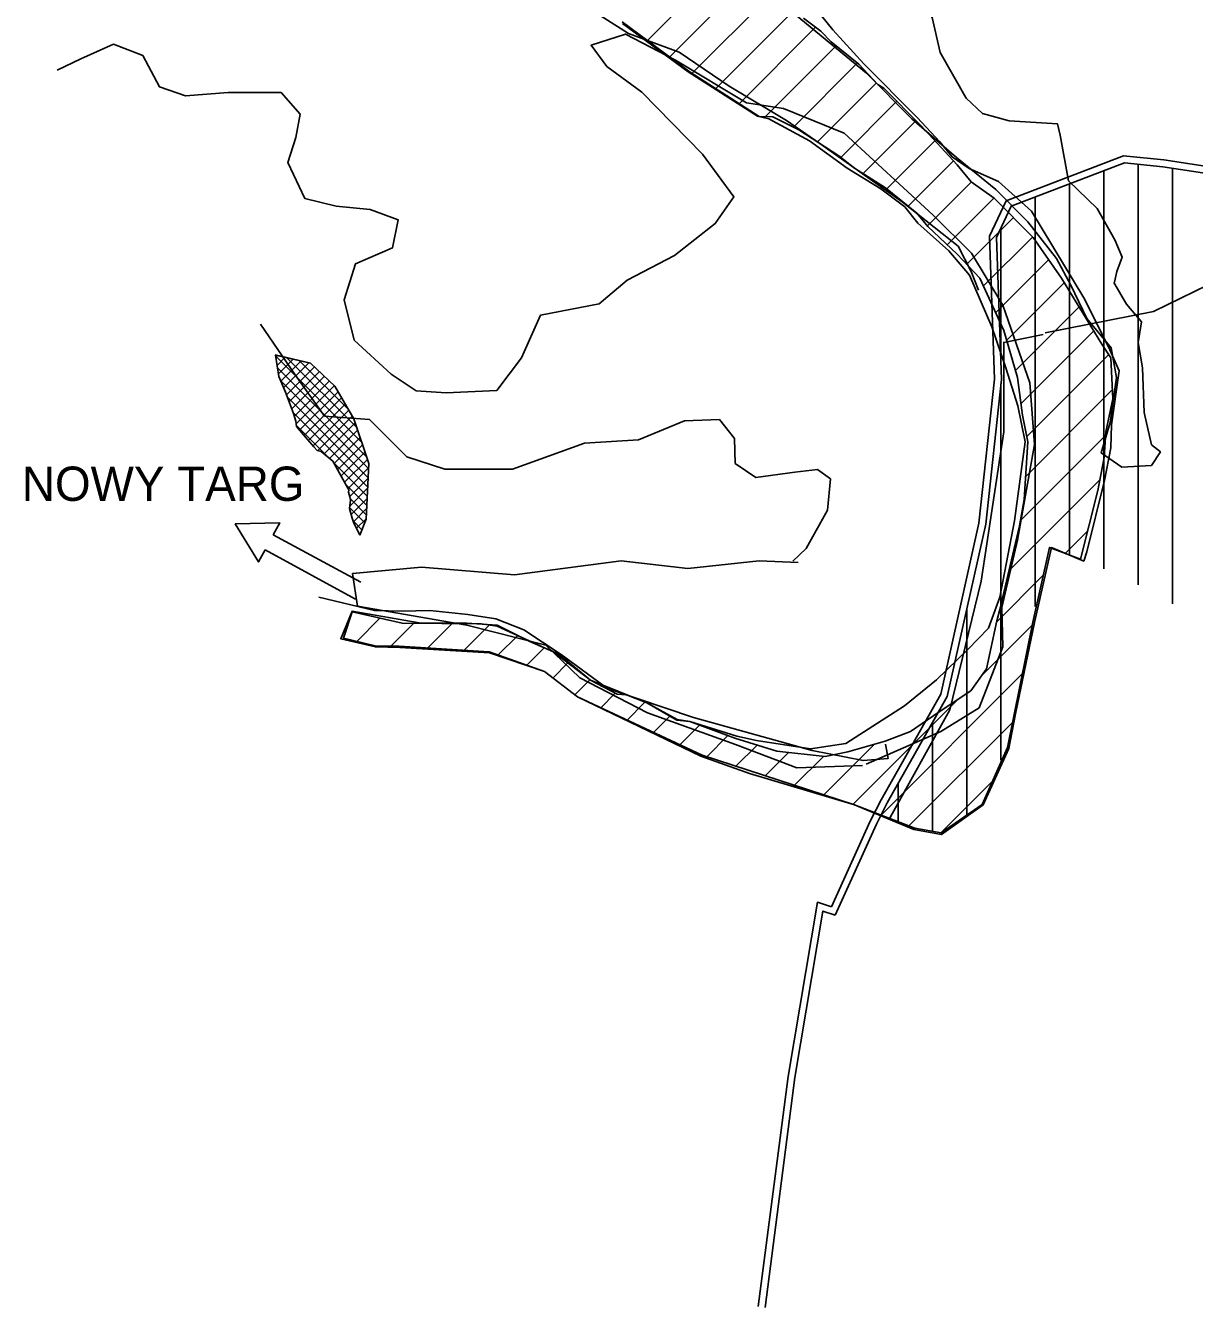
# Model space of a CAD drawing. Extents: x -562861 to -547287, y 190696 to 208158.
# Drawn here: x -559895 to -558190, y 195518 to 197388 of the extents above; entities that cross this region are included whole.
import ezdxf

# ---------------------------------------------------------------- set-up
doc = ezdxf.new("R2010")
doc.units = 0
for name, color, linetype in [('EKO - gr-OChK', 7, 'Continuous'), ('EKO - gr-PPK', 7, 'Continuous'), ('EKO - gr-PPK-otulina', 7, 'Continuous'), ('EKO - strefa ekologiczna', 7, 'Continuous'), ('EKO1 - ter_erozyjne', 7, 'Continuous'), ('EKO2 - erozja full', 7, 'Continuous'), ('natura_2000', 7, 'Continuous'), ('RZGW_100letnia', 7, 'Continuous'), ('str zal bezposr_zagr', 7, 'Continuous'), ('strzałki', 7, 'Continuous')]:
    doc.layers.add(name, color=color, linetype=linetype)

msp = doc.modelspace()

# ---------------------------------------------------------------- linework, layer by layer
at = {"layer": 'EKO - gr-OChK'}
for points in [[(-558719.6, 196102.3), (-558663.1, 196227.2), (-558647.2, 196258.5), (-558560.2, 196412.6), (-558504.6, 196662), (-558481.8, 196871.9), (-558489, 197080.5), (-558464.7, 197132.3), (-558293.5, 197197.8), (-558234.9, 197191.8), (-558082.6, 197168.6)], [(-558826.5, 195519.2), (-558783.2, 195854.8), (-558740.2, 196109), (-558719.6, 196102.3)]]:
    msp.add_lwpolyline(points, dxfattribs=at)
at = {"layer": 'EKO - gr-PPK'}
for p, q in [((-558272.5, 196571.8), (-558272.5, 197185.6)), ((-558222.5, 196544.2), (-558222.5, 197179.8)), ((-558322.5, 196595.1), (-558322.5, 197176)), ((-558372.5, 196615.6), (-558372.5, 197156.9)), ((-558422.5, 196540.1), (-558422.5, 197137.8)), ((-558472.5, 196892.2), (-558472.5, 197092.2)), ((-558472.5, 196316.2), (-558472.5, 196865)), ((-558522.5, 196235.8), (-558522.5, 196535.9)), ((-558572.5, 196213.4), (-558572.5, 196370.5)), ((-558622.5, 196225.8), (-558622.5, 196282))]:
    msp.add_line(p, q, dxfattribs=at)
for points in [[(-558085.3, 197158.9), (-558236.2, 197181.9), (-558292.2, 197187.6), (-558457.4, 197124.4), (-558479, 197078.4), (-558471.8, 196871.5), (-558494.8, 196660.4), (-558550.8, 196408.9), (-558638.4, 196253.8), (-558654.1, 196222.8)], [(-558654.1, 196222.8), (-558714.2, 196090.1)], [(-558714.2, 196090.1), (-558732.3, 196095.9), (-558773.3, 195853.3), (-558816.5, 195517.9)]]:
    msp.add_lwpolyline(points, dxfattribs=at)
at = {"layer": 'EKO - gr-PPK-otulina'}
for points in [[(-559082.7, 197418.3), (-559015.9, 197376.2), (-558941.9, 197348.8), (-558868.8, 197299.3), (-558785.2, 197249.1), (-558736.9, 197215.7), (-558616.8, 197130.4), (-558535.1, 197066.1), (-558516.1, 197028.8), (-558505.1, 197001.7)], [(-558641.1, 196339.4), (-558637.1, 196318.6), (-558673.7, 196315.6), (-558748, 196330.4), (-558921.3, 196378.6), (-559046.4, 196420.7), (-559114, 196470.4), (-559168.5, 196506.2), (-559209.4, 196522.3), (-559250.2, 196528.5), (-559305.9, 196534.7), (-559346.8, 196533.4), (-559386.4, 196534.7), (-559467.7, 196553.9)]]:
    msp.add_lwpolyline(points, dxfattribs=at)
at = {"layer": 'EKO - strefa ekologiczna'}
for points in [[(-558557.5, 197591.2), (-558592.4, 197585.8), (-558636.9, 197559.6), (-558639.5, 197525.6), (-558618.6, 197473.3), (-558572.8, 197399.3), (-558561, 197348.3), (-558523.1, 197281.6), (-558499.6, 197259.4), (-558460.4, 197248.9), (-558389.8, 197244.3), (-558385.9, 197228), (-558374.1, 197161.3), (-558332.3, 197120.7), (-558306.2, 197075), (-558295.7, 197050.1), (-558303.5, 197029.2), (-558307.1, 197013.3)], [(-558307.8, 197012.9), (-558289.5, 196981.5), (-558267.3, 196955.4), (-558272.5, 196925.3), (-558266, 196888.7), (-558263.4, 196823.3), (-558252.9, 196776.2), (-558239.9, 196765.7), (-558252.9, 196746.1), (-558296.1, 196743.5), (-558326.1, 196764.4), (-558313.1, 196808.9), (-558303.9, 196874.3), (-558311.8, 196917.4), (-558347.1, 196960.6), (-558370.6, 197009), (-558391.5, 197048), (-558433.3, 197101.6), (-558480.1, 197148.4), (-558537.6, 197195.5), (-558602.7, 197251.5), (-558668.7, 197318.3), (-558802.8, 197429)], [(-559282.1, 196852), (-559208.2, 196855.3), (-559172.1, 196902.9), (-559144.2, 196965.3), (-559058.9, 196981.7), (-559017.9, 197016.2), (-558948.9, 197052.3), (-558889.3, 197098.9), (-558862, 197137.7), (-558907.9, 197200.1), (-558996.5, 197290.4), (-559047.4, 197328.2), (-559070.4, 197358.9), (-559020.3, 197375.2), (-558947.3, 197337.5), (-558843.9, 197275.2), (-558789.8, 197266.9), (-558701.1, 197230.8), (-558571.5, 197111), (-558515.7, 197055.5), (-558469.7, 196979.9), (-558430.3, 196866.6), (-558423.8, 196776.8), (-558448.4, 196637.2), (-558471.4, 196538.7), (-558469.7, 196481.3), (-558504.2, 196392.6), (-558560, 196358), (-558669, 196310.1)], [(-559849.3, 197322.8), (-559814.8, 197339.2), (-559767.2, 197360.5), (-559724.6, 197344.1), (-559699.9, 197298.2), (-559662.2, 197285), (-559599.8, 197289.9), (-559522.7, 197289.9), (-559494.8, 197258.7), (-559501.4, 197224.3), (-559512.8, 197188.1), (-559488.2, 197135.6), (-559442.3, 197124.1), (-559393, 197119.2), (-559352, 197104.4), (-559360.2, 197063.3), (-559414.4, 197040.4), (-559430.8, 196987.8), (-559416, 196928.7), (-559361.9, 196879.4), (-559325.8, 196854.8), (-559282.1, 196852)], [(-558776, 196606.2), (-558756.8, 196625), (-558725.8, 196681), (-558721.3, 196726.4), (-558740.2, 196740), (-558773.4, 196736.2), (-558830.1, 196728.6), (-558860.3, 196749), (-558861.1, 196785.3), (-558883.3, 196812.9), (-558934.2, 196811.3), (-559001.5, 196783.4), (-559080.2, 196778.4), (-559185.3, 196740.7), (-559283.7, 196740.7), (-559339.5, 196758.7), (-559393.7, 196812.9), (-559459.3, 196817.9), (-559502, 196878.3), (-559552.9, 196952.2)], [(-558674.3, 196308.5), (-558770.1, 196305.1), (-558859.9, 196339.2), (-558988.1, 196385), (-559087, 196436.3), (-559136.4, 196484), (-559251.8, 196513.3), (-559411.1, 196540.8), (-559418.5, 196588.4), (-559317.7, 196597.6), (-559182.2, 196586.6), (-559026.5, 196606.7), (-558929.5, 196595.8), (-558825.1, 196606.7), (-558768.3, 196604.5)]]:
    msp.add_lwpolyline(points, dxfattribs=at)
at = {"layer": 'EKO1 - ter_erozyjne'}
for points in [[(-559531.2, 196907.2), (-559479.9, 196895.1), (-559444.3, 196861.5), (-559416.6, 196814), (-559394.9, 196748.8), (-559398.8, 196667.7), (-559407.7, 196644.5)], [(-559407.7, 196644.5), (-559398.8, 196667.7), (-559394.9, 196748.8), (-559416.6, 196814), (-559444.3, 196861.5), (-559479.9, 196895.1), (-559530.9, 196907.1)], [(-559530.9, 196907.1), (-559525.9, 196875.8), (-559516.4, 196852.9), (-559504.7, 196822), (-559501.2, 196810.9), (-559500.3, 196803), (-559490.1, 196790.9), (-559474.8, 196773.3), (-559470.1, 196767.9)], [(-559470.1, 196767.9), (-559464.2, 196766.5), (-559447.1, 196752.4), (-559425.3, 196713), (-559424, 196710.7), (-559424.6, 196707.1), (-559422.4, 196700.4), (-559421.5, 196695.4), (-559423.1, 196683.2), (-559419.2, 196669.4), (-559417.1, 196663.5), (-559407.7, 196644.5)]]:
    msp.add_lwpolyline(points, dxfattribs=at)
at = {"layer": 'EKO2 - erozja full'}
for p, q in [((-559530.6, 196905.4), (-559405.3, 196780)), ((-559530.5, 196904.2), (-559528.2, 196906.5)), ((-559528.5, 196892), (-559516.7, 196903.8)), ((-559526.6, 196879.8), (-559505.3, 196901.1)), ((-559523.1, 196869.1), (-559493.9, 196898.4)), ((-559514.3, 196903.2), (-559412.3, 196801.2)), ((-559495.8, 196898.9), (-559424.4, 196827.5)), ((-559528, 196888.5), (-559398.2, 196758.8)), ((-559519, 196859.1), (-559482.4, 196895.7)), ((-559514.9, 196849.1), (-559474.2, 196889.8)), ((-559511, 196838.8), (-559466.9, 196882.9)), ((-559523.5, 196869.9), (-559395.2, 196741.7)), ((-559507.1, 196828.5), (-559459.7, 196876)), ((-559503.4, 196818.1), (-559452.4, 196869.1)), ((-559500.7, 196806.7), (-559445.1, 196862.3)), ((-559445.1, 196862.3), (-559444.2, 196861.4)), ((-559513.8, 196846.1), (-559395.9, 196728.2)), ((-559495.7, 196797.6), (-559439.7, 196853.6)), ((-559489.2, 196789.9), (-559434.5, 196844.6)), ((-559505.2, 196823.4), (-559396.5, 196714.7)), ((-559482.7, 196782.3), (-559429.3, 196835.7)), ((-559476.1, 196774.7), (-559424, 196826.8)), ((-559500.4, 196804.5), (-559454.4, 196758.4)), ((-559469, 196767.7), (-559418.8, 196817.8)), ((-559459.7, 196762.8), (-559414.6, 196808)), ((-559452, 196756.4), (-559411.1, 196797.3)), ((-559445.2, 196749), (-559407.5, 196786.7)), ((-559440.2, 196739.9), (-559404, 196776.1)), ((-559445.4, 196749.4), (-559397.2, 196701.2)), ((-559435.1, 196730.8), (-559400.4, 196765.5)), ((-559430.1, 196721.7), (-559396.9, 196754.9)), ((-559425, 196712.6), (-559395.2, 196742.5)), ((-559427.9, 196717.8), (-559397.8, 196687.7)), ((-559422.6, 196700.9), (-559395.9, 196727.7)), ((-559422.6, 196686.8), (-559396.6, 196712.8)), ((-559421.9, 196697.7), (-559398.5, 196674.2)), ((-559420.7, 196674.6), (-559397.3, 196697.9)), ((-559422.9, 196684.5), (-559400.8, 196662.4)), ((-559417.3, 196663.9), (-559398.1, 196683.1)), ((-559417.7, 196665.2), (-559404.7, 196652.2)), ((-559412.6, 196654.4), (-559398.8, 196668.2)), ((-559407.9, 196644.9), (-559407.2, 196645.6))]:
    msp.add_line(p, q, dxfattribs=at)
for points in [[(-559531.2, 196907.2), (-559479.9, 196895.1), (-559444.3, 196861.5), (-559416.6, 196814), (-559394.9, 196748.8), (-559398.8, 196667.7), (-559407.7, 196644.5)], [(-559407.7, 196644.5), (-559398.8, 196667.7), (-559394.9, 196748.8), (-559416.6, 196814), (-559444.3, 196861.5), (-559479.9, 196895.1), (-559530.9, 196907.1)], [(-559530.9, 196907.1), (-559525.9, 196875.8), (-559516.4, 196852.9), (-559504.7, 196822), (-559501.2, 196810.9), (-559500.3, 196803), (-559490.1, 196790.9), (-559474.8, 196773.3), (-559470.1, 196767.9)], [(-559470.1, 196767.9), (-559464.2, 196766.5), (-559447.1, 196752.4), (-559425.3, 196713), (-559424, 196710.7), (-559424.6, 196707.1), (-559422.4, 196700.4), (-559421.5, 196695.4), (-559423.1, 196683.2), (-559419.2, 196669.4), (-559417.1, 196663.5), (-559407.7, 196644.5)]]:
    msp.add_lwpolyline(points, dxfattribs=at)
at = {"layer": 'natura_2000'}
for points in [[(-558408.1, 196939.5), (-558250, 196970.5), (-558170.1, 197009.6), (-558051.1, 197009.6), (-557892.9, 196908.5), (-557773.9, 196918.3), (-557713.6, 196911.8), (-557604.3, 196862.9), (-557405.4, 196828.7), (-557309.2, 196773.3), (-557063, 196791.2), (-556912.7, 196786), (-556733.6, 196753.1), (-556702.7, 196738.6), (-556636.8, 196734.5), (-556604.2, 196721.7), (-556572.7, 196647.2), (-556567, 196598.5), (-556617.1, 196513.9), (-556626.6, 196512.3), (-557036.2, 196567.9), (-557052.7, 196547.3), (-557042.4, 196146)], [(-558636.1, 196229), (-558547.3, 196389.5), (-558501.4, 196577.3), (-558468.4, 196795.1), (-558468.4, 196925.5), (-558411.1, 196937)]]:
    msp.add_lwpolyline(points, dxfattribs=at)
at = {"layer": 'RZGW_100letnia'}
msp.add_lwpolyline([(-558752.7, 197425.1), (-558718, 197381.5), (-558672.4, 197332), (-558595, 197253.6), (-558561.6, 197218.3), (-558543.5, 197196.3), (-558518.7, 197179), (-558476.1, 197160.3), (-558428.2, 197117.1), (-558351.6, 196990.8), (-558315.4, 196919.2), (-558300.3, 196884.1), (-558311.4, 196805.3), (-558312.4, 196771.6), (-558321.3, 196724), (-558347.1, 196620), (-558351.7, 196606.6), (-558398.8, 196626.2), (-558423.5, 196517.2), (-558451.5, 196383.9), (-558460.9, 196333.4), (-558498.4, 196251.1), (-558559.1, 196207.7), (-558599.5, 196215), (-558686.1, 196251.1), (-558839.6, 196296.6), (-558910.6, 196322.1), (-559090.1, 196408.5), (-559138.5, 196445.3), (-559218.6, 196472.7), (-559349.3, 196480.7), (-559385, 196481.4), (-559435.6, 196493.3), (-559419.1, 196533.3), (-559318.2, 196516.2), (-559258.9, 196516.7), (-559207.7, 196513.1), (-559160, 196489.1), (-559117.3, 196470.8), (-559071.4, 196432.8), (-558989, 196399.6), (-558944.8, 196375.7), (-558926.5, 196372.7), (-558858, 196351.1), (-558829.1, 196345), (-558750.2, 196332.9), (-558698.7, 196340.6), (-558613.1, 196395.3), (-558566.5, 196433.3), (-558520.8, 196477.7), (-558490.8, 196508.9), (-558474.3, 196554.1), (-558452.6, 196665.1), (-558437.3, 196780.6), (-558447.9, 196833), (-558465.4, 196888.7), (-558485.6, 196948.5), (-558518.4, 197023.8), (-558548.7, 197059.2), (-558593.9, 197099.3), (-558612.7, 197123.2), (-558647.7, 197149.4), (-558697.1, 197179.5), (-558751.9, 197219.5), (-558811.2, 197251.7), (-558827.5, 197255.8), (-558928.9, 197320.4), (-559024.7, 197390.9)], dxfattribs=at)
at = {"layer": 'str zal bezposr_zagr'}
for p, q in [((-558988.3, 197366), (-558863.5, 197490.8)), ((-558955.7, 197342), (-558831.9, 197465.9)), ((-558923.1, 197318.1), (-558802.7, 197438.5)), ((-558888.7, 197295.9), (-558773.7, 197410.9)), ((-558854.3, 197273.8), (-558742.9, 197385.2)), ((-558816.7, 197254.8), (-558713, 197358.4)), ((-558775.3, 197239.6), (-558682.1, 197332.8)), ((-558740.3, 197218.1), (-558654.2, 197304.1)), ((-558706.3, 197195.5), (-558624.4, 197277.4)), ((-558673.5, 197171.7), (-558596.1, 197249.1)), ((-558639.1, 197149.6), (-558568.7, 197219.9)), ((-558607.7, 197124.4), (-558541.7, 197190.4)), ((-558579.9, 197095.6), (-558515.6, 197159.9)), ((-558550.9, 197068.1), (-558482.8, 197136.1)), ((-558522.5, 197039.9), (-558454.4, 197107.9)), ((-558497.9, 197007.9), (-558426.2, 197079.6)), ((-558480.3, 196968.9), (-558402.9, 197046.3)), ((-558464.2, 196928.5), (-558380.1, 197012.6)), ((-558451.4, 196884.7), (-558358.6, 196977.5)), ((-558443.2, 196836.3), (-558337.1, 196942.4)), ((-558434.8, 196788.1), (-558315.2, 196907.8)), ((-558436.7, 196729.7), (-558310.1, 196856.3)), ((-558444.2, 196665.6), (-558319.6, 196790.2)), ((-558460.8, 196592.4), (-558328.2, 196725)), ((-558378.9, 196617.8), (-558346, 196650.6)), ((-558479, 196517.6), (-558410.9, 196585.8)), ((-559412.4, 196489.4), (-559378.7, 196523.1)), ((-559362.6, 196482.6), (-559329.5, 196515.7)), ((-559308.8, 196479.8), (-559273.3, 196515.3)), ((-559255.5, 196476.6), (-559218.7, 196513.4)), ((-558500.5, 196439.6), (-558427.1, 196513)), ((-559205.9, 196469.6), (-559177.5, 196498)), ((-559164.3, 196454.6), (-559138.7, 196480.2)), ((-559126.3, 196436), (-559104.4, 196458)), ((-559094.2, 196411.6), (-559072.3, 196433.5)), ((-558647.5, 196236), (-558441.4, 196442.1)), ((-559056.5, 196392.7), (-559035.3, 196413.9)), ((-559018, 196374.7), (-558991.9, 196400.7)), ((-558688.3, 196251.8), (-558535, 196405.2)), ((-558979.4, 196356.7), (-558955.6, 196380.5)), ((-558940.9, 196338.6), (-558912.2, 196367.3)), ((-558606.8, 196220.2), (-558455.7, 196371.2)), ((-558901.8, 196321.2), (-558871, 196352)), ((-558859.1, 196307.3), (-558828.3, 196338.1)), ((-558731, 196265.7), (-558657.1, 196339.5)), ((-558816.4, 196293.4), (-558782.6, 196327.2)), ((-558773.7, 196279.5), (-558731.6, 196321.6)), ((-558560.3, 196210.1), (-558485, 196285.4))]:
    msp.add_line(p, q, dxfattribs=at)
msp.add_lwpolyline([(-559025.2, 197393.3), (-558925.7, 197319.8), (-558825.3, 197255.1), (-558805.4, 197254.5), (-558767.3, 197235.7), (-558708.9, 197197.6), (-558686.3, 197179.9), (-558640.8, 197150.9), (-558595.1, 197114.3), (-558579, 197094.4), (-558536.2, 197054.3), (-558503.2, 197019.5), (-558468.4, 196942.7), (-558448.3, 196874.4), (-558441, 196819.5), (-558433.3, 196780.4), (-558438.8, 196696.5), (-558445.5, 196658), (-558474, 196536.1), (-558478.6, 196519.5), (-558493.4, 196449.4), (-558516.7, 196417.3), (-558562.5, 196386.8), (-558604.4, 196358.1), (-558641.6, 196344.1), (-558696, 196328.1), (-558729.1, 196321.3), (-558799.5, 196329.1), (-558860.7, 196348.2), (-558926.5, 196372.7), (-558945.3, 196374.7), (-558989, 196399.6), (-559018.8, 196411.3), (-559032.6, 196412.4), (-559071.4, 196432.8), (-559126.7, 196475), (-559137.7, 196479.7), (-559207.4, 196511.8), (-559231, 196515.1), (-559346.2, 196515.8), (-559419.1, 196532.3), (-559431.8, 196494.2), (-559385.7, 196482.8), (-559350.7, 196482.4), (-559219.1, 196474.3), (-559138.5, 196445.3), (-559090.1, 196408.5), (-558908.2, 196323.3), (-558686.1, 196251.1), (-558598.4, 196216.9), (-558559.8, 196210), (-558500.1, 196251.6), (-558463.2, 196334.4), (-558426.2, 196517.5), (-558401.7, 196626.5), (-558356.5, 196609.2), (-558331.2, 196709.5), (-558322, 196757.7), (-558319.3, 196795), (-558309.5, 196843.2), (-558312, 196903), (-558325.2, 196923), (-558384.2, 197019.3), (-558425.3, 197078.8), (-558482.3, 197135.8), (-558515.8, 197160), (-558536.2, 197184.4), (-558589.2, 197242.2), (-558643.3, 197296.3), (-558652, 197301.8), (-558680.1, 197331.2), (-558720, 197364.2), (-558735.5, 197379.8), (-558760.6, 197398.4)], dxfattribs=at)
at = {"layer": 'strzałki'}
for p, q in [((-559406.6, 196575.7), (-559534.1, 196644.9)), ((-559414, 196551.2), (-559546.1, 196622.9))]:
    msp.add_line(p, q, dxfattribs=at)
msp.add_lwpolyline([(-559534.1, 196644.9), (-559524.6, 196662.4), (-559589.6, 196660.7), (-559555.6, 196605.3), (-559546.1, 196622.9)], dxfattribs=at)

# ---------------------------------------------------------------- texts
msp.add_text('NOWY TARG', height=50, dxfattribs=at).set_placement((-559900.9, 196694.4))

doc.saveas('drawing.dxf')
